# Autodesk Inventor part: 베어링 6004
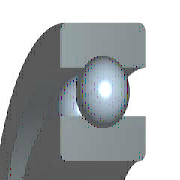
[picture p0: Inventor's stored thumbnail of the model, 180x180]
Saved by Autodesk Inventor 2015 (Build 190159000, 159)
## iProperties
Created: 2012-02
Part Number: 베어링 6004
Material: 강철, 연강
Description: 깊은 그루브 볼 베어링
Document SubType Name: Modeling
Standard: KS B 2023
Designer: mduedu
Standards Organization: KS
Language: ko-KR
Size Designation: 6004 - 20 x 42 x 12
Categories: <MemberInstance><Categories><Category DisplayName="샤프트 부품" InternalName="7f7aeb1f-a693-4053-b835-cee3144e0d98" Mnemonic="SHFT"><Category DisplayName="베어링" Inter
Density: 1 g/cm^3
Appearance: 노란색
IsCustomPart: 1
Author: mduedu
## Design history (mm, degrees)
sketch "스케치" dims "d0" = 5.72 (= -0.26 x WD + 0.26 x BD)
  geometry: L1 (3.14, 15.5)-(8.86, 15.5); L2 (6, 15.5)-(6, 12.64); L3 (6, 15.5)-(6, 18.36); L4 (3.875, 13.586)-(0, 13.586); L5 (0, 10)-(12, 10); L6 (3.875, 17.414)-(0, 17.414); L7 (0, 21)-(12, 21); L8 (12, 10)-(12, 13.586); L9 (8.125, 13.586)-(12, 13.586); L10 (8.125, 17.414)-(12, 17.414); L11 (12, 21)-(12, 17.414); L12 (-1.4, 0)-(8.4, 0) reference; L13 (0, -0.3)-(0, 5.3) reference
  constraints: 22 end point, 4 point on line, 2 collinear, 2 perpendicular, 2 symmetric about line, 1 midpoint, 1 parallel, 14 other
  dimensions: "d9" = 20 diameter of L5 L12 (= WD); "d11" = 42 diameter of L7 L12 (= BD); "d12" = 12 distance between parallel lines of L8 L13 (= KB); "d13" = 27.172 diameter of L9 L12 (= 0.326 x BD + 0.674 x WD)
revolve "본체" stored, may be unused: angle "d6" = 90 deg
revolve "볼" stored, may be unused: angle "d7" = 90 deg
pattern_circular "IDS_ARRAYBALL[SIMPL:T]" dims angle "d3" = 360 deg
body "Solid1"
fillet "모깎기1" dims "d1" = 0.6 (= KRS)
other parameters: "WD" = 20 [user parameter; used in 5 equation terms], "BD" = 42 [user parameter; used in 5 equation terms], "KB" = 12 [user parameter; used in 1 equation term], "KRS" = 0.6 [user parameter; used in 1 equation term], "d4" = 0, "d5" = 0, "d8" = 0, "d14" = 0, "d15" = 0, "BBA" = 0 [user parameter], "BC0" = 5000000 [user parameter], "BC" = 9360000 [user parameter], "BR" = 21 (= 0.5 x BD) [user parameter]
